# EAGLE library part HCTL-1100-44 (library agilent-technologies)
General Purpose Motion Controller provides position and velocity control for DC, DC brushless and stepper motors. Source: http://www.avagotech.com/pc/downloadDocument.do?id=4609
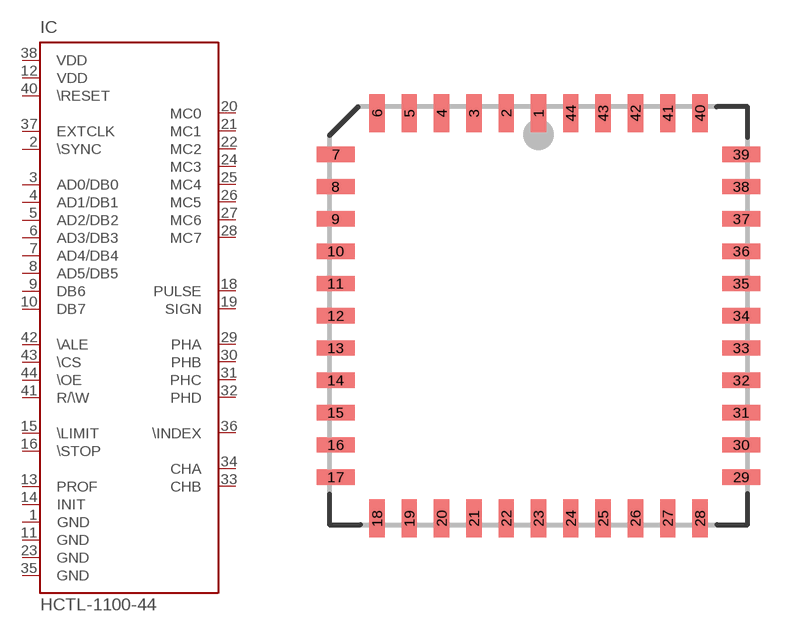
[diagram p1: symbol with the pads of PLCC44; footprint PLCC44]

Designator prefix IC

## HCTL-1100-44  [PLCC44]
1  GND  pwr
2  \SYNC  in
3  AD0/DB0
4  AD1/DB1
5  AD2/DB2
6  AD3/DB3
7  AD4/DB4
8  AD5/DB5
9  DB6
10  DB7
11  GND  pwr
12  VDD  pwr
13  PROF  out
14  INIT  out
15  \LIMIT  in
16  \STOP  in
18  PULSE  out
19  SIGN  out
20  MC0  out
21  MC1  out
22  MC2  out
23  GND  pwr
24  MC3  out
25  MC4  out
26  MC5  out
27  MC6  out
28  MC7  out
29  PHA  out
30  PHB  out
31  PHC  out
32  PHD  out
33  CHB  in
34  CHA  in
35  GND  pwr
36  \INDEX  in
37  EXTCLK  in
38  VDD  pwr
40  \RESET  in
41  R/\W  in
42  \ALE  in
43  \CS  in
44  \OE  in

## Footprint PLCC44 (pad centres in mm)
PLASTIC LEADED CHIP CARRIER http://www.avagotech.com/pc/downloadDocument.do?id=4609
smd 0.6 x 1.5: 1 0,7.975; 2 -1.27,7.975; 3 -2.54,7.975; 4 -3.81,7.975; 5 -5.08,7.975; 6 -6.35,7.975; 18 -6.35,-7.975; 19 -5.08,-7.975; 20 -3.81,-7.975; 21 -2.54,-7.975; 22 -1.27,-7.975; 23 0,-7.975; 24 1.27,-7.975; 25 2.54,-7.975; 26 3.81,-7.975; 27 5.08,-7.975; 28 6.35,-7.975; 40 6.35,7.975; 41 5.08,7.975; 42 3.81,7.975; 43 2.54,7.975; 44 1.27,7.975
smd 1.5 x 0.6: 7 -7.975,6.35; 8 -7.975,5.08; 9 -7.975,3.81; 10 -7.975,2.54; 11 -7.975,1.27; 12 -7.975,0; 13 -7.975,-1.27; 14 -7.975,-2.54; 15 -7.975,-3.81; 16 -7.975,-5.08; 17 -7.975,-6.35; 29 7.975,-6.35; 30 7.975,-5.08; 31 7.975,-3.81; 32 7.975,-2.54; 33 7.975,-1.27; 34 7.975,0; 35 7.975,1.27; 36 7.975,2.54; 37 7.975,3.81; 38 7.975,5.08; 39 7.975,6.35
